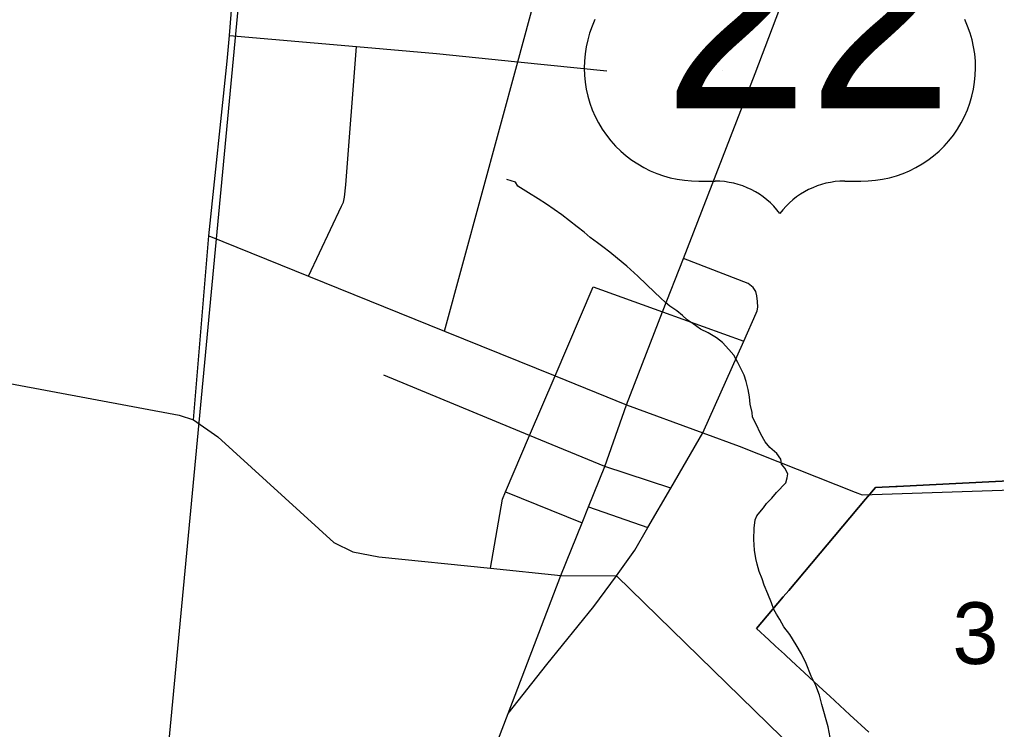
# Model space of a CAD drawing. Extents: x 0 to 34, y -3.9 to 26.2.
# Drawn here: x 8.005 to 8.667, y 19.156 to 19.638 of the extents above; entities that cross this region are included whole.
import ezdxf

# ---------------------------------------------------------------- set-up
doc = ezdxf.new("R2010")
doc.units = 0
for name, color, linetype in [('GM_X_City_Street', 7, 'Continuous'), ('GM_X_County_Road', 7, 'Continuous'), ('GM_X_Interchange_Ramps', 7, 'Continuous'), ('GM_X_Minor_River', 7, 'Continuous'), ('GM_X_Section', 7, 'Continuous'), ('GM_X_Section_Text', 7, 'Continuous'), ('GM_X_State_Route', 7, 'Continuous'), ('GM_X_State_Shield', 7, 'Continuous'), ('GM_X_US_Location', 7, 'Continuous'), ('GM_X_US_Route', 7, 'Continuous'), ('GM_X_US_Shield', 7, 'Continuous')]:
    doc.layers.add(name, color=color, linetype=linetype)

msp = doc.modelspace()

# ---------------------------------------------------------------- linework, layer by layer
at = {"layer": 'GM_X_City_Street'}
for p, q in [((8.33415, 19.31739), (8.38604, 19.29626)), ((8.39038, 19.30708), (8.43071, 19.2931))]:
    msp.add_line(p, q, dxfattribs=at)
for points in [[(8.12248, 19.36621), (8.13282, 19.49101), (8.14543, 19.60943), (8.14683, 19.62694), (8.1685, 19.89854), (7.88287, 19.97021)], [(8.29285, 19.4263), (8.34243, 19.60909), (8.35467, 19.65421), (8.35596, 19.66141), (8.35785, 19.67808), (8.3606, 19.71679), (8.36031, 19.72098), (8.36007, 19.72249), (8.35923, 19.72452), (8.35823, 19.72623), (8.35667, 19.72753), (8.35394, 19.72847), (8.34874, 19.7296), (8.33435, 19.73068), (8.25538, 19.72845), (8.25382, 19.72792), (8.25262, 19.72715), (8.25115, 19.72554), (8.2505, 19.72403), (8.2465, 19.68587)], [(8.14683, 19.62694), (8.23296, 19.61941), (8.28741, 19.61465), (8.34243, 19.60909), (8.40285, 19.60298)], [(8.2004, 19.46369), (8.22293, 19.51118), (8.22422, 19.51386), (8.22495, 19.51721), (8.2259, 19.52556), (8.23296, 19.61941)], [(8.13282, 19.49101), (8.2004, 19.46369), (8.29285, 19.4263), (8.36774, 19.39603), (8.41622, 19.37642)], [(8.33583, 19.16696), (8.36212, 19.20023), (8.39394, 19.23958), (8.40934, 19.26038), (8.42176, 19.27764), (8.43071, 19.2931), (8.44616, 19.31978), (8.46789, 19.3573), (8.49566, 19.41958), (8.50406, 19.43842), (8.50468, 19.44), (8.50521, 19.44264), (8.50508, 19.44643), (8.50465, 19.45021), (8.50387, 19.45327), (8.50208, 19.45586), (8.49866, 19.45861), (8.45473, 19.47566)], [(8.32399, 19.26542), (8.33196, 19.31226), (8.33415, 19.31739), (8.35046, 19.35557), (8.36774, 19.39603), (8.39356, 19.45647)], [(8.39356, 19.45647), (8.44068, 19.43945), (8.49566, 19.41958)], [(8.44616, 19.31978), (8.40136, 19.3345), (8.35046, 19.35557), (8.25151, 19.39652)], [(8.37173, 19.26055), (8.40934, 19.26038), (8.57754, 19.09621)]]:
    msp.add_lwpolyline(points, dxfattribs=at)
at = {"layer": 'GM_X_County_Road'}
msp.add_lwpolyline([(7.76077, 19.4352), (8.1127, 19.36932), (8.12248, 19.36621), (8.13893, 19.35465), (8.21758, 19.28294), (8.23057, 19.27663), (8.24823, 19.27314), (8.32399, 19.26542), (8.37173, 19.26055)], dxfattribs=at)
at = {"layer": 'GM_X_Interchange_Ramps'}
for points in [[(8.5804, 19.15414), (8.5677, 19.16597), (8.55401, 19.17871), (8.54958, 19.18281), (8.53372, 19.19747), (8.53129, 19.19972), (8.52417, 19.20629), (8.52332, 19.20708), (8.51724, 19.21265), (8.51263, 19.21687), (8.50434, 19.22447), (8.52245, 19.24597), (8.52614, 19.25035), (8.57829, 19.31226), (8.57983, 19.3141), (8.58496, 19.32018), (8.59873, 19.32086), (8.59967, 19.3209), (8.62158, 19.32199), (8.64413, 19.3231), (8.6665, 19.32421), (8.68933, 19.32534)], [(8.68933, 19.32534), (8.6665, 19.32421), (8.64413, 19.3231), (8.62158, 19.32199), (8.59967, 19.3209), (8.59873, 19.32086), (8.58496, 19.32018), (8.57983, 19.3141), (8.57829, 19.31226), (8.52614, 19.25035), (8.52245, 19.24597), (8.50434, 19.22447), (8.51263, 19.21687), (8.51724, 19.21265), (8.52332, 19.20708), (8.52417, 19.20629), (8.53129, 19.19972), (8.53372, 19.19747), (8.54958, 19.18281), (8.55401, 19.17871), (8.5677, 19.16597), (8.5804, 19.15414)]]:
    msp.add_lwpolyline(points, dxfattribs=at)
at = {"layer": 'GM_X_Minor_River'}
for points in [[(8.5269, 19.22057), (8.52291, 19.22567), (8.52006, 19.23073), (8.51791, 19.23424), (8.51613, 19.23735), (8.51441, 19.24198), (8.51199, 19.24817), (8.50955, 19.25397), (8.50819, 19.25821), (8.50611, 19.26324), (8.50479, 19.26823), (8.5038, 19.27208), (8.50289, 19.27782), (8.50242, 19.28506), (8.50274, 19.29266), (8.50336, 19.29834), (8.50461, 19.30095), (8.50663, 19.30353), (8.50904, 19.30648), (8.51108, 19.30944), (8.51467, 19.3131), (8.51788, 19.31678), (8.52427, 19.32337), (8.52518, 19.32676), (8.52567, 19.3294), (8.52354, 19.33329), (8.52135, 19.33604), (8.52073, 19.33949), (8.51822, 19.34339), (8.51341, 19.34739), (8.51013, 19.35132), (8.50728, 19.35638), (8.50377, 19.36375), (8.50165, 19.36802), (8.50139, 19.37107), (8.5001, 19.37683), (8.49954, 19.38179), (8.4986, 19.38678), (8.49729, 19.39216), (8.49594, 19.39639), (8.4917, 19.40493), (8.48886, 19.40999), (8.48558, 19.41392), (8.48118, 19.41866), (8.47711, 19.42187), (8.47151, 19.42513), (8.46626, 19.42762), (8.46144, 19.43124), (8.45735, 19.43407), (8.45403, 19.43686), (8.45034, 19.44005), (8.4455, 19.44329), (8.44254, 19.44569), (8.43923, 19.44886), (8.43519, 19.45282), (8.42967, 19.45799), (8.42378, 19.46355), (8.41641, 19.47031), (8.41013, 19.47551), (8.40496, 19.4799), (8.40014, 19.48351), (8.39643, 19.48632), (8.39161, 19.48994), (8.38755, 19.49352), (8.38273, 19.49714), (8.37236, 19.50516), (8.36195, 19.51242), (8.35637, 19.51607), (8.34965, 19.52014), (8.34258, 19.5246), (8.34078, 19.52734), (8.33511, 19.52908)], [(8.55422, 19.15063), (8.55299, 19.15791), (8.54864, 19.17292), (8.547, 19.17945), (8.54459, 19.18601), (8.54141, 19.19222), (8.53793, 19.20073), (8.53477, 19.20732), (8.5312, 19.21355), (8.5269, 19.22057)]]:
    msp.add_lwpolyline(points, dxfattribs=at)
at = {"layer": 'GM_X_Section'}
msp.add_lwpolyline([(7.22341, 19.93622), (8.16495, 19.7765), (8.06934, 18.76306), (7.12087, 18.93735)], close=True, dxfattribs=at)
at = {"layer": 'GM_X_State_Route'}
for p, q in [((8.44068, 19.43945), (8.45473, 19.47566)), ((8.41622, 19.37642), (8.44068, 19.43945)), ((8.40136, 19.3345), (8.41622, 19.37642)), ((8.39038, 19.30708), (8.40136, 19.3345)), ((8.38604, 19.29626), (8.39038, 19.30708)), ((8.37173, 19.26055), (8.38604, 19.29626)), ((8.33583, 19.16696), (8.37173, 19.26055)), ((8.31101, 19.10224), (8.33583, 19.16696))]:
    msp.add_line(p, q, dxfattribs=at)
for points in [[(8.45473, 19.47566), (8.50337, 19.60102), (8.57069, 19.77887), (8.57266, 19.78366)], [(8.41622, 19.37642), (8.46789, 19.3573), (8.49255, 19.34816), (8.57126, 19.3171)], [(8.57126, 19.3171), (8.57594, 19.31525), (8.6844, 19.31888), (8.79142, 19.32561), (8.88054, 19.33096), (8.9, 19.33199)]]:
    msp.add_lwpolyline(points, dxfattribs=at)
at = {"layer": 'GM_X_State_Shield'}
msp.add_lwpolyline([(8.9, 18.80132), (8.9, 19.81071), (8.16495, 19.7765), (8.06934, 18.76306)], close=True, dxfattribs=at)
at = {"layer": 'GM_X_US_Route'}
for p, q in [((8.44068, 19.43945), (8.45473, 19.47566)), ((8.41622, 19.37642), (8.44068, 19.43945)), ((8.40136, 19.3345), (8.41622, 19.37642)), ((8.39038, 19.30708), (8.40136, 19.3345)), ((8.38604, 19.29626), (8.39038, 19.30708)), ((8.37173, 19.26055), (8.38604, 19.29626)), ((8.33583, 19.16696), (8.37173, 19.26055)), ((8.31101, 19.10224), (8.33583, 19.16696))]:
    msp.add_line(p, q, dxfattribs=at)
msp.add_lwpolyline([(8.45473, 19.47566), (8.50337, 19.60102), (8.57069, 19.77887), (8.57266, 19.78366)], dxfattribs=at)
at = {"layer": 'GM_X_US_Shield'}
for p, q in [((8.46525, 19.5281), (8.47623, 19.5281)), ((8.56412, 19.5281), (8.57511, 19.5281))]:
    msp.add_line(p, q, dxfattribs=at)
for centre, radius, start, end in [((8.46439, 19.605), 0.0769, 154.83192, 270.63826), ((8.57597, 19.605), 0.0769, 269.36174, 25.16808), ((8.47623, 19.47317), 0.05493, 36.8699, 90), ((8.56412, 19.47317), 0.05493, 90, 143.1301)]:
    msp.add_arc(centre, radius, start, end, dxfattribs=at)

# ---------------------------------------------------------------- texts
at = {"layer": 'GM_X_Section_Text'}
msp.add_text('3', height=0.04186, rotation=0.00001, dxfattribs=at).set_placement((8.63726, 19.20049))
at = {"layer": 'GM_X_US_Location'}
msp.add_text('22', height=0.000189, rotation=0.00001, dxfattribs=at).set_placement((8.48101, 19.60322))
at = {"layer": 'GM_X_US_Shield'}
msp.add_text('22', height=0.131836, dxfattribs=at).set_placement((8.44141, 19.57754))

doc.saveas('drawing.dxf')
